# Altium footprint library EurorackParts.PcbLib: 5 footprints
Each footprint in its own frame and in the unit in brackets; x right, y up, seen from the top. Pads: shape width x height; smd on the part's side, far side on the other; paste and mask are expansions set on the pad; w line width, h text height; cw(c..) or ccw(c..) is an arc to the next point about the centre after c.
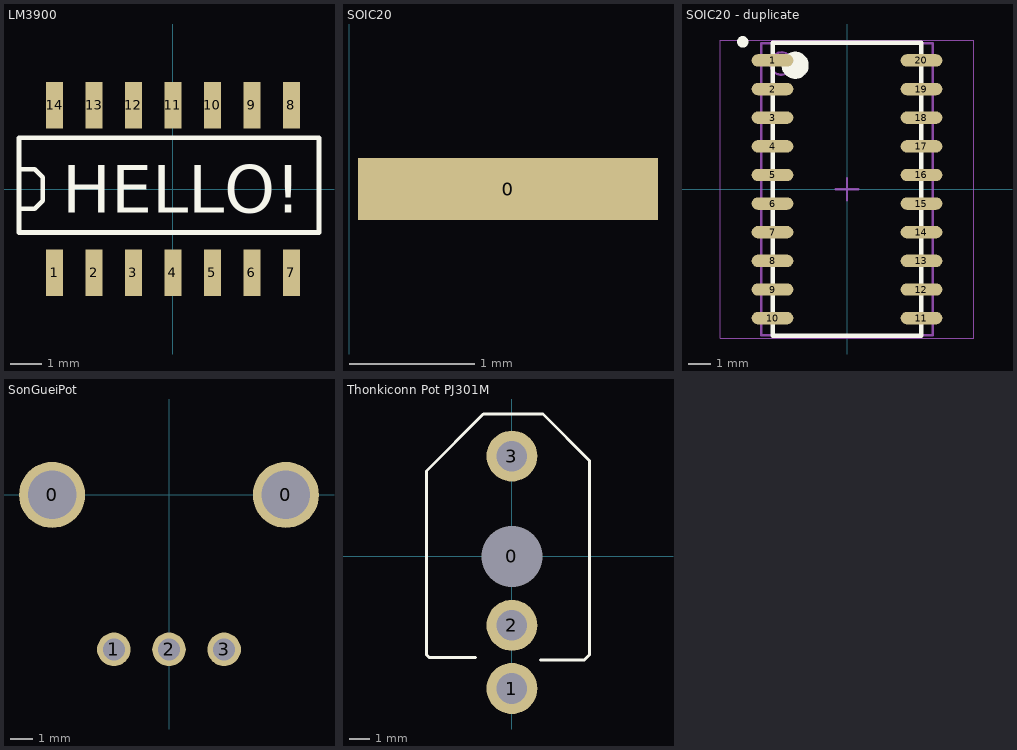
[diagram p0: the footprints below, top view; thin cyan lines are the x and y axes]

## LM3900 [mm] "LM3900 SOIC"
height 0.002
pads (14):
  rect 0.55x1.5 smd: 1(-3.81,-2.7) 2(-2.54,-2.7) 3(-1.27,-2.7) 4(0,-2.7) 5(1.27,-2.7) 6(2.54,-2.7) 7(3.81,-2.7) 8(3.81,2.7) 9(2.54,2.7) 10(1.27,2.7) 11(0,2.7) 12(-1.27,2.7) 13(-2.54,2.7) 14(-3.81,2.7)
Top Overlay:
  lines w0.152: -4.953,-0.635 -4.445,-0.635 -4.191,-0.381 -4.191,0.381 -4.445,0.635 -4.953,0.635 ; -4.953,-1.397 4.699,-1.397 4.699,1.651 -4.953,1.651 -4.953,-1.397
  text "HELLO!" at -3.556,-0.762 h1.52

## SOIC20 [mm] "20 pin SOIC"
height 1.8
pads (1):
  rect 2.4x0.5 smd: 0(1.27,1.397)

## SOIC20 - duplicate [mm]
pads (20):
  oval 1.85x0.55 smd: 1(-3.302,5.715) 2(-3.302,4.445) 3(-3.302,3.175) 4(-3.302,1.905) 5(-3.302,0.635) 6(-3.302,-0.635) 7(-3.302,-1.905) 8(-3.302,-3.175) 9(-3.302,-4.445) 10(-3.302,-5.715) 11(3.302,-5.715) 12(3.302,-4.445) 13(3.302,-3.175) 14(3.302,-1.905) 15(3.302,-0.635) 16(3.302,0.635) 17(3.302,1.905) 18(3.302,3.175) 19(3.302,4.445) 20(3.302,5.715)
Top Overlay:
  circle w0.25: c-4.625,6.54 r0.125
  circle w0.6: c-2.3,5.5 r0.3
  lines w0.2: -3.3,-6.5 -3.3,6.5 3.3,6.5 3.3,-6.5 -3.3,-6.5
Mechanical 13:
  circle w0.1: c-2.9,5.575 r0.5
  lines w0.1: -3.8,-6.475 -3.8,6.475 3.8,6.475 3.8,-6.475 -3.8,-6.475
Mechanical 15:
  lines w0.05: -5.625,-6.6 -5.625,6.6 5.625,6.6 5.625,-6.6 -5.625,-6.6
  lines w0.1: -0.5,0 0.5,0 ; 0,-0.5 0,0.5
3D body: height 2.65, standoff 0.1, extent -3.8,-6.475 3.8,6.475

## SonGueiPot [mm]
pads (5):
  round 3 hole 2.2: 0(-5.3,0) 0(5.3,0)
  round 1.524 hole 1: 1(-2.5,-7) 2(0,-7) 3(2.5,-7)
3D body "9mmAlpha.step": height 20, standoff -3.8, extent -4.876,-7.235 4.876,5.315

## Thonkiconn Pot PJ301M [mm] "PJ301 Thonkicon Jack from Thonk"
height 0.368
pads (4):
  round 1.524 hole 3: 0(0,0)
  round 2.5 hole 1.5: 1(0,-6.48) 2(0,-3.38) 3(0,4.92)
Top Overlay:
  lines w0.152: -1.778,-4.953 -4.064,-4.953 -4.191,-4.826 -4.191,4.191 -1.397,6.985 1.524,6.985 3.81,4.699 3.81,-4.826 3.556,-5.08 1.397,-5.08
3D body "mj-3507.stp": height 14, standoff -5.6, extent -4.555,-10.286 4.445,5.714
